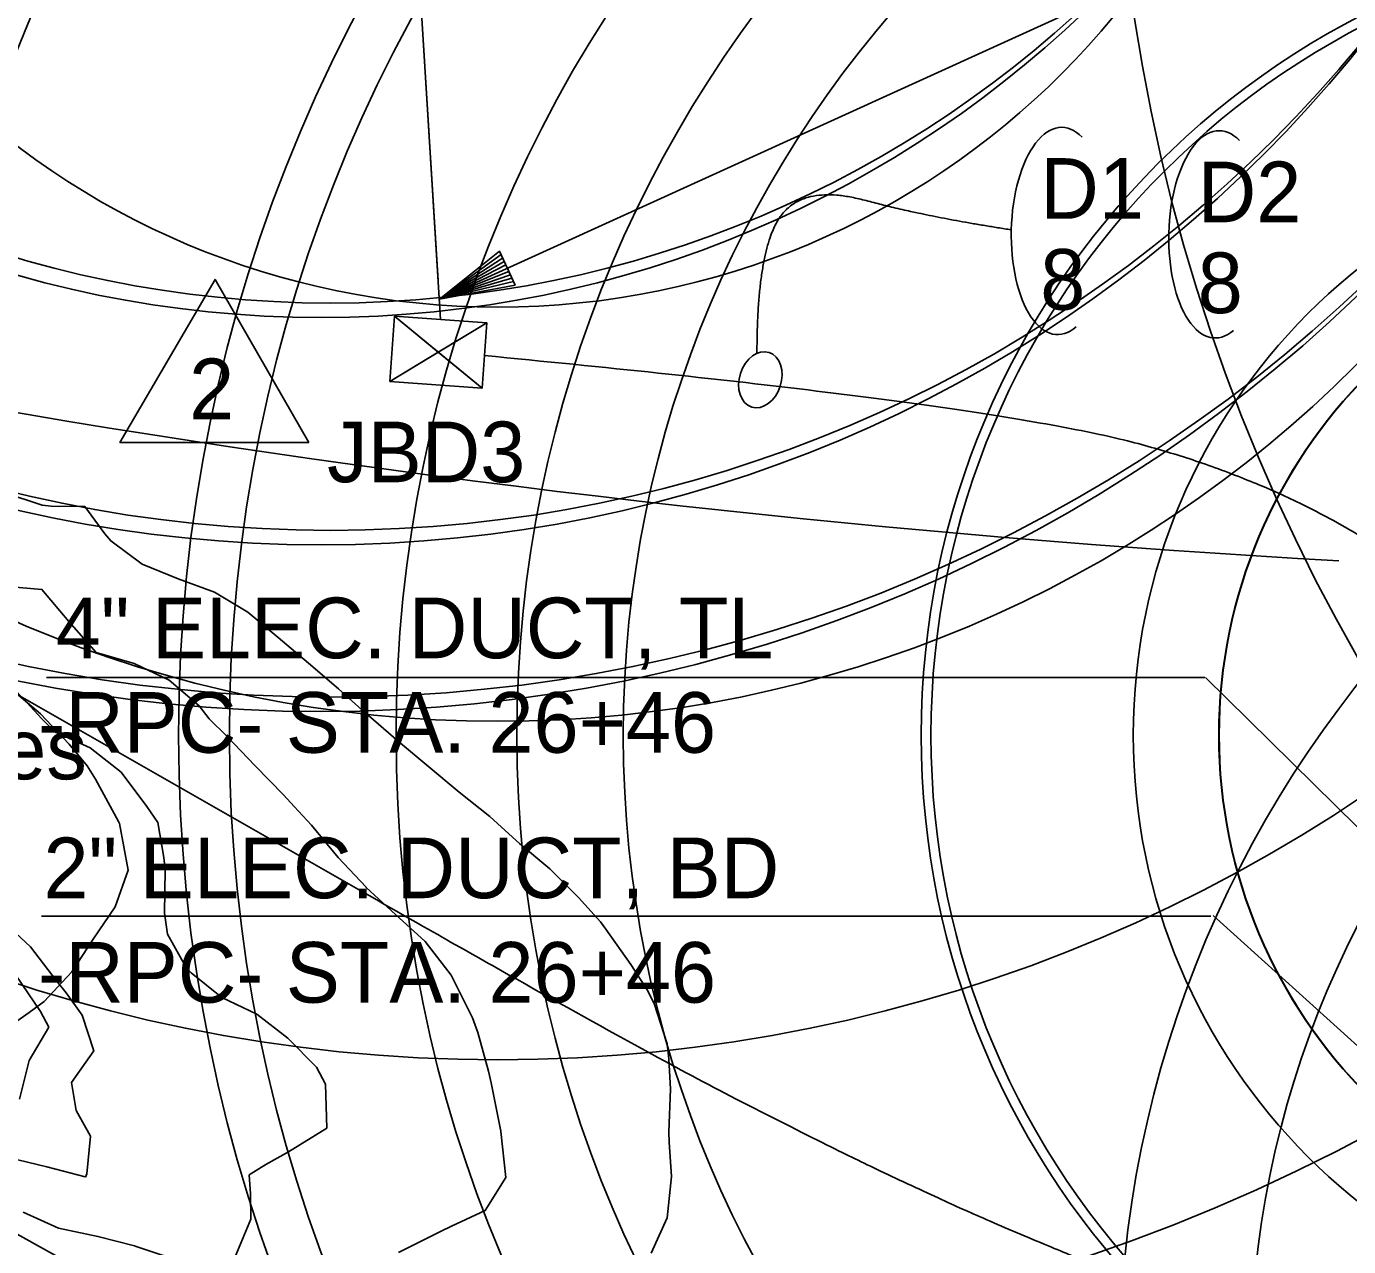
# Model space of a CAD drawing. Extents: x 1638506 to 1658005, y 834807 to 846788.
# Drawn here: x 1640958.6 to 1641220.4, y 842171.5 to 842413 of the extents above; entities that cross this region are included whole.
import ezdxf

# ---------------------------------------------------------------- set-up
doc = ezdxf.new("R2010")
doc.units = 0
for name, color, linetype in [('Default', 7, 'Continuous'), ('Old_Level_1', 7, 'Continuous'), ('Old_Level_2', 7, 'Continuous'), ('Old_Level_4', 7, 'Continuous'), ('Scratch_Level_0', 7, 'Continuous')]:
    doc.layers.add(name, color=color, linetype=linetype)

msp = doc.modelspace()

# ---------------------------------------------------------------- linework, layer by layer
at = {"layer": 'Default'}
for p, q in [((1641040.34, 842359.02), (1641350.44, 842500.06)), ((1641032.47, 842485.48), (1641040.59, 842354.99)), ((1641040.11, 842362.65), (1641032.89, 842478.66)), ((1641031.47, 842355.65), (1641048.78, 842341.41)), ((1641030.54, 842342.72), (1641049.71, 842354.34)), ((1640962.57, 842284.11), (1641191.89, 842284.11)), ((1641192.01, 842284.15), (1641394.9, 842084.34)), ((1640961.55, 842236.91), (1641193.07, 842236.91)), ((1641193.58, 842237.04), (1641398.04, 842051.93)), ((1640921.33, 842193.61), (1641098.15, 842095.33))]:
    msp.add_line(p, q, dxfattribs=at)
msp.add_lwpolyline([(1641053.81, 842365.14), (1641054.11, 842364.47), (1641040.34, 842359.02), (1641054.4, 842363.84), (1641054.7, 842363.17), (1641040.34, 842359.02), (1641055.01, 842362.49), (1641055.32, 842361.82), (1641040.34, 842359.02), (1641052.23, 842368.49), (1641052.58, 842367.84), (1641040.34, 842359.02), (1641052.84, 842367.14), (1641053.19, 842366.49), (1641040.34, 842359.02), (1641053.5, 842365.82), (1641055.32, 842361.82), (1641052.23, 842368.49), (1641040.34, 842359.02), (1641055.32, 842361.82)], dxfattribs=at)
for points in [[(1641014.47, 842330.65), (1640977.08, 842330.65), (1640995.91, 842362.92)], [(1641031.47, 842355.65), (1641049.71, 842354.34), (1641048.78, 842341.41), (1641030.54, 842342.72)], [(1641040.12, 842348.53), (1641030.54, 842342.72), (1641031.47, 842355.65)], [(1641040.12, 842348.53), (1641048.78, 842341.41), (1641049.71, 842354.34)]]:
    msp.add_lwpolyline(points, close=True, dxfattribs=at)
for centre, start_param, end_param in [((1641163.16, 842372.52), 2.710831, 4.712389), ((1641194.35, 842371.85), 2.710831, 4.712389), ((1641163.16, 842372.52), 4.712389, 6.681485), ((1641194.35, 842371.85), 4.712389, 6.681485)]:
    msp.add_ellipse(centre, major_axis=(-0.49, -20.52), ratio=0.466223, start_param=start_param, end_param=end_param, dxfattribs=at)
msp.add_ellipse((1641103.9, 842343.06), major_axis=(1.72, 5.4), ratio=0.730797, dxfattribs=at)
for points in [[(1641103.22, 842348.29), (1641103.22, 842368.69), (1641112.36, 842381.87), (1641136.92, 842375.28), (1641153.59, 842372.75)], [(1641049.24, 842347.87), (1641150.23, 842338.18), (1641208.08, 842322.42), (1641250.53, 842293.31), (1641269.36, 842249.14), (1641286.54, 842249.14)]]:
    msp.add_open_spline(points, degree=2, dxfattribs=at)
at = {"layer": 'Old_Level_1'}
for points in [[(1640977.02, 842255.2), (1640976.79, 842255.64), (1640972.25, 842264.02), (1640970.57, 842266.65), (1640967.03, 842270.93), (1640961.38, 842276.92), (1640955.33, 842282.04)], [(1640954.9, 842214.87), (1640959.13, 842217.78), (1640962.07, 842219.96), (1640967.58, 842225.84), (1640971.77, 842232.32), (1640976.12, 842238.74), (1640978.68, 842245.98), (1640977.02, 842255.2)]]:
    msp.add_lwpolyline(points, dxfattribs=at)
for centre, radius in [((1641016.92, 842574.38), 297), ((1641016.92, 842574.38), 264), ((1641016.92, 842574.38), 219), ((1641295.68, 842272.71), 365), ((1641295.68, 842272.71), 307), ((1641295.68, 842272.71), 240), ((1641295.68, 842272.71), 158), ((1641295.68, 842272.71), 101)]:
    msp.add_circle(centre, radius, dxfattribs=at)
at = {"layer": 'Old_Level_2'}
msp.add_line((1640832.25, 842351.83), (1641022.96, 842242.94), dxfattribs=at)
msp.add_arc((1641349.38, 844661.61), 2358.01, 254.10061, 266.81673, dxfattribs=at)
msp.add_open_spline([(1641022.96, 842242.94), (1641038.01, 842234.35), (1641052.83, 842225.89), (1641082.21, 842209.62), (1641096.78, 842201.8), (1641118.55, 842190.83), (1641125.8, 842187.29), (1641140.28, 842180.52), (1641147.52, 842177.28), (1641161.99, 842171.13), (1641169.22, 842168.22), (1641180.07, 842164.14), (1641183.68, 842162.83), (1641189.11, 842160.94), (1641190.91, 842160.32), (1641192.94, 842159.64), (1641193.17, 842159.56), (1641193.42, 842159.48), (1641193.43, 842159.48), (1641193.44, 842159.47), (1641193.46, 842159.47), (1641193.5, 842159.45), (1641193.54, 842159.44), (1641193.61, 842159.42), (1641193.66, 842159.4), (1641193.71, 842159.38), (1641193.72, 842159.38), (1641193.74, 842159.37), (1641193.76, 842159.37), (1641193.81, 842159.35), (1641193.92, 842159.31), (1641194, 842159.29), (1641194.16, 842159.23), (1641194.27, 842159.2), (1641194.48, 842159.13), (1641194.81, 842159.02), (1641195.15, 842158.91), (1641196.3, 842158.53), (1641197.27, 842158.21), (1641198.3, 842157.88)], degree=3, dxfattribs=at)
at = {"layer": 'Old_Level_4'}
for centre, radius in [((1641051.91, 842515.45), 365), ((1641538.84, 842469.72), 365), ((1641051.91, 842515.45), 307), ((1641051.91, 842515.45), 240), ((1641051.91, 842515.45), 158), ((1641393.92, 842146.92), 219), ((1641393.92, 842146.92), 193)]:
    msp.add_circle(centre, radius, dxfattribs=at)
at = {"layer": 'Scratch_Level_0'}
for points in [[(1641086.27, 842185.33), (1641085.85, 842192.17), (1641085.8, 842194.2), (1641086.13, 842202.65), (1641085.77, 842208.62), (1641085.41, 842211.64), (1641082.86, 842219.61), (1641081.51, 842222.28), (1641078.26, 842227.34), (1641073.27, 842234.33), (1641072.21, 842235.74), (1641067.88, 842240.56), (1641062.23, 842246.28), (1641056.2, 842251.26), (1641052.62, 842254.53), (1641050.36, 842256.62), (1641044.23, 842261.4), (1641038.22, 842266.43), (1641032.21, 842271.46), (1641026.27, 842276.63), (1641025.65, 842277.16), (1641020.37, 842281.86), (1641014.39, 842286.94), (1641008.44, 842292.07), (1641002.39, 842297.03), (1640995.83, 842301), (1640988.58, 842303.63), (1640981.47, 842306.55), (1640975.25, 842311.16), (1640974.08, 842312.57), (1640970.16, 842317.96), (1640963.49, 842318.07), (1640961.67, 842318.21), (1640954.32, 842320.65)], [(1641052.51, 842194.25), (1641052.49, 842194.34), (1641050.56, 842203.88), (1641050.04, 842206.21), (1641047.94, 842213.86), (1641046.91, 842216.78), (1641042.66, 842225.2), (1641042.64, 842225.23), (1641037.5, 842231.85), (1641031.66, 842237.21), (1641025.86, 842242.57), (1641025.84, 842242.59), (1641020.29, 842248.51), (1641014.99, 842254.9), (1641011.57, 842258.62), (1641009.47, 842260.87), (1641003.83, 842266.62), (1640998.26, 842272.48), (1640994.77, 842275.96), (1640992.76, 842278.5), (1640986.8, 842283.62), (1640979.88, 842286.9), (1640972.38, 842289.05), (1640966.97, 842295.22), (1640961.64, 842301.57), (1640953.39, 842302.28)], [(1641017.81, 842203.65), (1641015.98, 842207.02), (1641010.33, 842212.74), (1641004.17, 842217.47), (1640997.28, 842220.81), (1640991.18, 842225.67), (1640990.28, 842226.57), (1640986.53, 842233.31), (1640985.93, 842237.45), (1640986.02, 842246.02), (1640985.79, 842248.48), (1640984.58, 842255.39), (1640982.43, 842258.61), (1640977.33, 842265.38), (1640971.2, 842270.18), (1640964.22, 842273.34), (1640961.62, 842275.94), (1640958.64, 842279.19), (1640953.05, 842285.02)], [(1640970.28, 842185.24), (1640970.5, 842185.86), (1640971.26, 842193.35), (1640968.41, 842198.42), (1640967.46, 842203.94), (1640971.91, 842210.25), (1640969.6, 842217.3), (1640966.41, 842221.73), (1640964.49, 842224.06), (1640959.38, 842230.82), (1640953.57, 842236.23)], [(1640963, 842214.88), (1640961.33, 842217.99), (1640956.44, 842225.17)], [(1640957.22, 842200.64), (1640959.09, 842208.29), (1640963, 842214.88)], [(1641000.03, 842169.78), (1641002.99, 842176.87), (1641002.93, 842181.89), (1641002.67, 842185.65), (1641005.97, 842187.75), (1641010.48, 842190.22), (1641018.02, 842194.92), (1641017.81, 842203.65)], [(1641032.25, 842170.29), (1641040.72, 842174.51), (1641042.72, 842175.51), (1641049.43, 842178.61), (1641053.49, 842185.12), (1641052.51, 842194.25)], [(1640954.97, 842189.14), (1640962.63, 842187.29), (1640970.19, 842185.25), (1640970.28, 842185.24)], [(1641082.25, 842170.18), (1641085.43, 842177.15), (1641086.27, 842185.33)], [(1640957.95, 842178.29), (1640964.92, 842175.11), (1640972.71, 842173.5), (1640979.94, 842171.6), (1640980.29, 842171.49), (1640987.63, 842169.04)]]:
    msp.add_lwpolyline(points, dxfattribs=at)
for centre, radius in [((1641018.82, 842577.25), 297), ((1641018.82, 842577.25), 264), ((1641018.82, 842577.25), 219), ((1641295.75, 842272.71), 297), ((1641295.75, 842272.71), 264), ((1641295.75, 842272.71), 219), ((1641295.75, 842272.71), 160), ((1641295.75, 842272.71), 118), ((1641295.75, 842272.71), 101)]:
    msp.add_circle(centre, radius, dxfattribs=at)

# ---------------------------------------------------------------- texts
at = {"layer": 'Default'}
for s, p in [('D1', (1641159.32, 842374.93)), ('D2', (1641190.5, 842374.25)), ('8', (1641159.32, 842356.93)), ('8', (1641190.5, 842356.25)), ('2', (1640990.78, 842335.26)), ('JBD3', (1641018.11, 842322.78)), ('4" ELEC. DUCT, TL', (1640964.36, 842287.94)), ('-RPC- STA. 26+46', (1640960.9, 842269.23)), ('2" ELEC. DUCT, BD', (1640961.94, 842240.44)), ('-RPC- STA. 26+46', (1640960.9, 842219.76))]:
    msp.add_text(s, height=12, dxfattribs=at).set_placement(p)
at = {"layer": 'Scratch_Level_0'}
msp.add_text('8x320W LED Fixtures', height=12, dxfattribs=at).set_placement((1640814.46, 842263.97))

doc.saveas('drawing.dxf')
